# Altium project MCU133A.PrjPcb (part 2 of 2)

## Sheet MCU133A_USB_and_Power.SchDoc
size 431 x 279 mm; Date: Not shown in title block; ApprovedBy: Not shown in title block; CheckedBy: Not shown in title block; Author: Not shown in title block; CompanyName: Not shown in title block; Engineer: Not shown in title block; Organization: Not shown in title block; Address1: Not shown in title block; Address2: Not shown in title block; Address3: Not shown in title block; Address4: Not shown in title block; DocumentNumber: 6; Revision: Use project parameter SCH_Rev; SheetNumber: 6; SheetTotal: 7; PageSetup: Record=PageOptions¦CenterHorizontal=True¦CenterVertical=True¦PrintScale=1.00¦XCorrection=1.00¦YCorrection=1.00¦PrintKind=0¦BorderSize=5000000¦LeftOffset=0¦BottomOffset=0¦Orientation=2¦PaperLength=1000¦PaperWidth=1000¦Scale=100¦PaperSource=15¦PrintQuality=600¦MediaType=1¦DitherType=10¦PaperKind=Letter¦PrintScaleMode=1
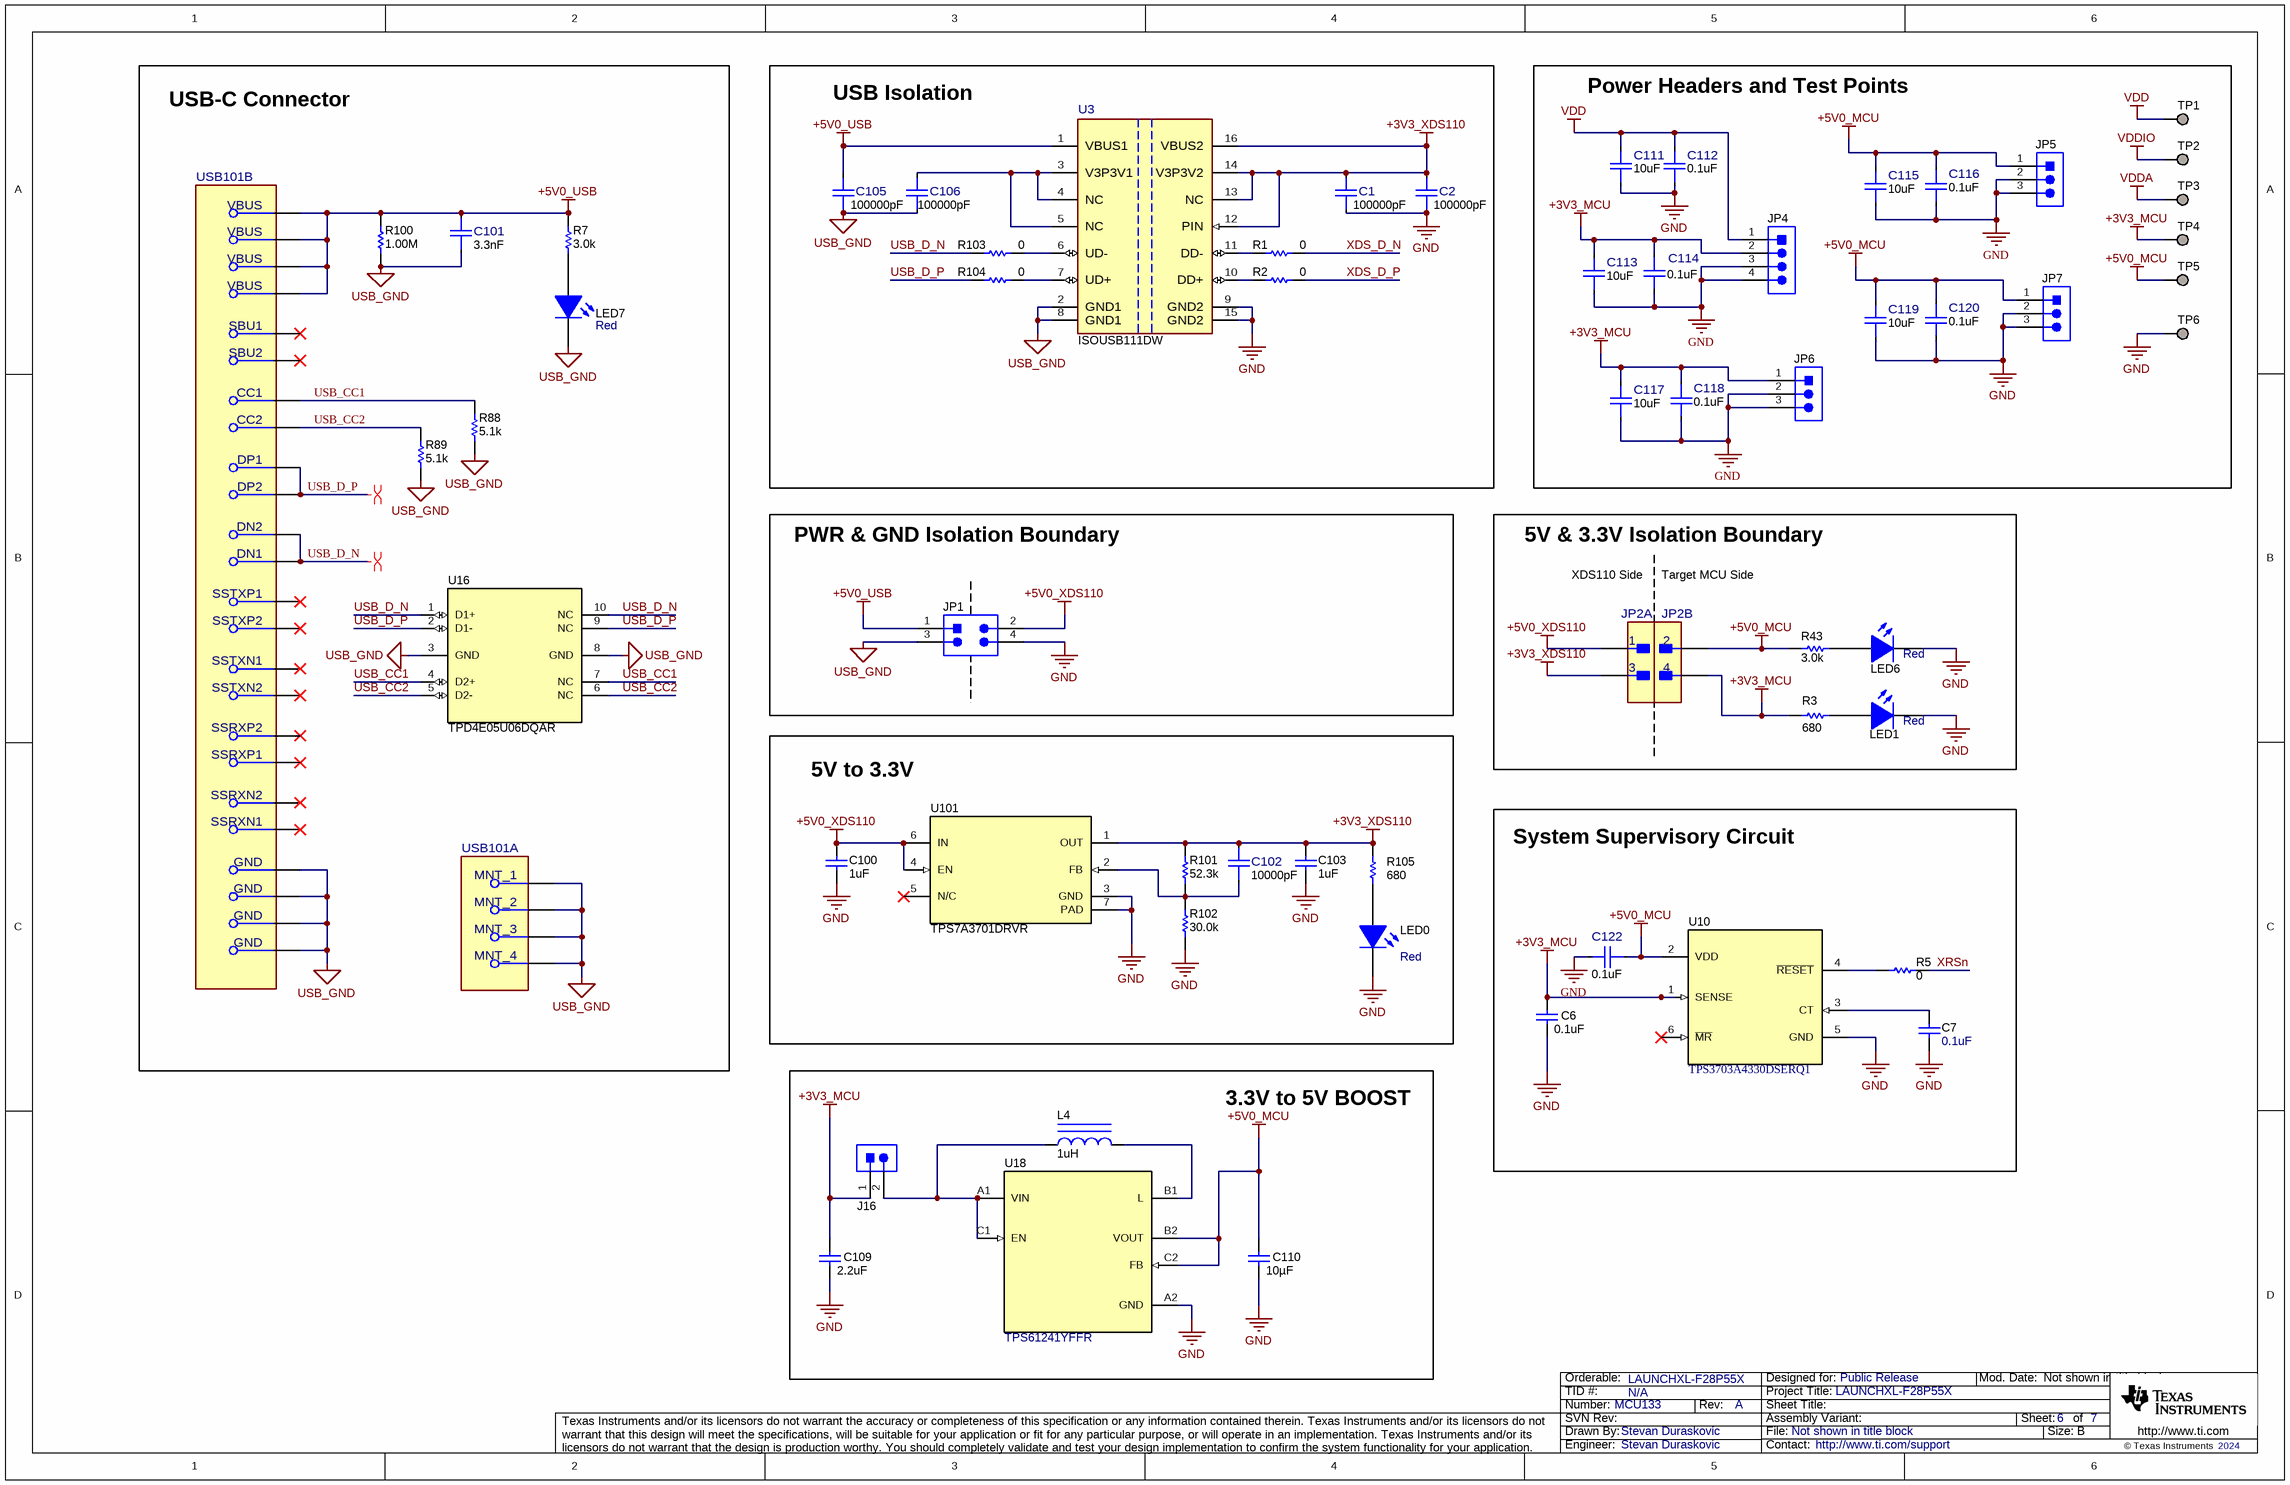
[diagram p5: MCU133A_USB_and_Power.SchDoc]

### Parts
C1  ValueDisplayed: 100000pF  [FP-885012205018_0402-MFG]  (hidden comment: 885012205018)
C2  ValueDisplayed: 100000pF  [FP-885012205018_0402-MFG]  (hidden comment: 885012205018)
C6  ValueDisplayed: 0.1uF  [0402]  (hidden comment: 885012205037)
C7  ValueDisplayed: 0.1uF  [0402]  (hidden comment: 885012205037)
C100  ValueDisplayed: 1uF  [0402]  (hidden comment: 885012105012)
C101  ValueDisplayed: 3.3nF  [FP-885012205064_0402-MFG]  (hidden comment: 885012205064)
C102  ValueDisplayed: 10000pF  [FP-885012205050_0402-MFG]  (hidden comment: 885012205050)
C103  ValueDisplayed: 1uF  [0402]  (hidden comment: 885012105012)
C105  ValueDisplayed: 100000pF  [FP-885012205018_0402-MFG]  (hidden comment: 885012205018)
C106  ValueDisplayed: 100000pF  [FP-885012205018_0402-MFG]  (hidden comment: 885012205018)
C109  ValueDisplayed: 2.2uF  [0603]  (hidden comment: 885012106018)
C110  ValueDisplayed: 10µF  [0603]  (hidden comment: GRM188R61C106KAALD)
C111  ValueDisplayed: 10uF  [FP-CC0603KRX5R6BB106_0603-MFG]  (hidden comment: CC0603KRX5R6BB106)
C112  ValueDisplayed: 0.1uF  [FP-885012205018_0402-MFG]  (hidden comment: 885012205018)
C113  ValueDisplayed: 10uF  [FP-CC0603KRX5R6BB106_0603-MFG]  (hidden comment: CC0603KRX5R6BB106)
C114  ValueDisplayed: 0.1uF  [FP-885012205018_0402-MFG]  (hidden comment: 885012205018)
C115  ValueDisplayed: 10uF  [FP-CC0603KRX5R6BB106_0603-MFG]  (hidden comment: CC0603KRX5R6BB106)
C116  ValueDisplayed: 0.1uF  [FP-885012205018_0402-MFG]  (hidden comment: 885012205018)
C117  ValueDisplayed: 10uF  [FP-CC0603KRX5R6BB106_0603-MFG]  (hidden comment: CC0603KRX5R6BB106)
C118  ValueDisplayed: 0.1uF  [FP-885012205018_0402-MFG]  (hidden comment: 885012205018)
C119  ValueDisplayed: 10uF  [FP-CC0603KRX5R6BB106_0603-MFG]  (hidden comment: CC0603KRX5R6BB106)
C120  ValueDisplayed: 0.1uF  [FP-885012205018_0402-MFG]  (hidden comment: 885012205018)
C122  ValueDisplayed: 0.1uF  [FP-885012205018_0402-MFG]  (hidden comment: 885012205018)
J16  61300211121  [WURTH_61300211121]  (value not drawn)
JP1  TSM-102-01-L-DV  [Samtec_TSM-102-01-x-DV]  (value not drawn)
JP2  61300421121  [FP-61300421121_HDR4-MFG]  (value not drawn)  (parts A,B of 2)
JP4  61300411121  [WURTH_61300411121]  (value not drawn)
JP5  61300311121  [WURTH_61300311121]  (value not drawn)
JP6  61300311121  [WURTH_61300311121]  (value not drawn)
JP7  61300311121  [WURTH_61300311121]  (value not drawn)
L4  ValueDisplayed: 1uH  [0805_HV]  (hidden comment: LQM21PN1R0MC0D)
LED0  value Red  [WL-SMCW_RED_0805]  (hidden comment: 150080SS75000)
LED1  value Red  [WL-SMCW_RED_0805]  (hidden comment: 150080SS75000)
LED6  value Red  [WL-SMCW_RED_0805]  (hidden comment: 150080SS75000)
LED7  value Red  [WL-SMCW_RED_0805]  (hidden comment: 150080SS75000)
R1  ValueDisplayed: 0  [0402]  (hidden comment: RC0402JR-070RL)
R2  ValueDisplayed: 0  [0402]  (hidden comment: RC0402JR-070RL)
R3  ValueDisplayed: 680  [0402]  (hidden comment: CRCW0402680RJNED)
R5  ValueDisplayed: 0  [0603]  (hidden comment: ERJ-3GEY0R00V)
R7  ValueDisplayed: 3.0k  [0603]  (hidden comment: RC0603JR-073KL)
R43  ValueDisplayed: 3.0k  [0603]  (hidden comment: RC0603JR-073KL)
R88  ValueDisplayed: 5.1k  [0603]  (hidden comment: RC0603JR-075K1L)
R89  ValueDisplayed: 5.1k  [0603]  (hidden comment: RC0603JR-075K1L)
R100  ValueDisplayed: 1.00M  [0402]  (hidden comment: CRCW04021M00FKED)
R101  ValueDisplayed: 52.3k  [0402]  (hidden comment: CRCW040252K3FKED)
R102  ValueDisplayed: 30.0k  [0402]  (hidden comment: CRCW040230K0FKED)
R103  ValueDisplayed: 0  [0402]  (hidden comment: RC0402JR-070RL)
R104  ValueDisplayed: 0  [0402]  (hidden comment: RC0402JR-070RL)
R105  ValueDisplayed: 680  [0402]  (hidden comment: CRCW0402680RJNED)
TP1  TESTPOINT  [TP_50MIL-25MILHOLE]  (value not drawn)  (no BOM)
TP2  TESTPOINT  [TP_50MIL-25MILHOLE]  (value not drawn)  (no BOM)
TP3  TESTPOINT  [TP_50MIL-25MILHOLE]  (value not drawn)  (no BOM)
TP4  TESTPOINT  [TP_50MIL-25MILHOLE]  (value not drawn)  (no BOM)
TP5  TESTPOINT  [TP_50MIL-25MILHOLE]  (value not drawn)  (no BOM)
TP6  TESTPOINT  [TP_50MIL-25MILHOLE]  (value not drawn)  (no BOM)
U3  ISOUSB111DW  [DW0016B-MFG]
U10  TPS3703A4330DSERQ1  [DSE0006A]
U16  TPD4E05U06DQAR  [DQA0010A]
U18  TPS61241YFFR  [YFF0006AEAE]
U101  TPS7A3701DRVR  [DRV0006A]
USB101  MUP-U22001  [FP-MUP-U22001_CONN_USB_8MM94_8MM0-MFG]  (value not drawn)  (parts A,B of 2)

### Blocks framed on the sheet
USB-C Connector: C101 LED7 R7 R88 R89 R100 U16 USB101
USB Isolation: C1 C2 C105 C106 R1 R2 R103 R104 U3
Power Headers and Test Points: C111-C120 JP4-JP7 TP1-TP6
PWR & GND Isolation Boundary: JP1
5V & 3.3V Isolation Boundary: JP2 LED1 LED6 R3 R43
5V to 3.3V: C100 C102 C103 LED0 R101 R102 R105 U101
System Supervisory Circuit: C6 C7 C122 R5 U10
3.3V to 5V BOOST: C109 C110 J16 L4 U18

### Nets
+3V3_MCU: C6.1 C109.1 C113.2 C114.1 C117.2 C118.1 J16.1 JP2.4 JP4.2 JP6.1 R3.2 TP4.1 U10.1(SENSE)
+3V3_XDS110: C1.2 C2.2 C102.2 C103.1 JP2.3 R101.2 R105.2 U3.12(PIN) U3.13(NC) U3.14(V3P3V2) U3.16(VBUS2) U101.1(OUT)
+5V0_MCU: C110.1 C115.2 C116.1 C119.2 C120.1 C122.1 JP2.2 JP5.1 JP7.1 R43.2 TP5.1 U10.2(VDD) U18.B2(VOUT) U18.C2(FB)
+5V0_USB: C101.2 C105.2 JP1.1 R7.2 R100.2 U3.1(VBUS1) USB101.A4(VBUS) USB101.A9(VBUS) USB101.B4(VBUS) USB101.B9(VBUS)
+5V0_XDS110: C100.1 JP1.2 JP2.1 U101.4(EN) U101.6(IN)
GND: C1.1 C2.1 C6.2 C7.2 C100.2 C103.2 C109.2 C110.2 C111.1 C112.1 C113.1 C114.2 C115.1 C116.2 C117.1 C118.2 C119.1 C120.2 C122.2 JP1.4 JP4.3 JP4.4 JP5.2 JP5.3 JP6.2 JP6.3 JP7.2 JP7.3 LED0.1(K) LED1.1(K) LED6.1(K) R102.1 TP6.1 U3.9(GND2) U3.15(GND2) U10.5(GND) U18.A2(GND) U101.3(GND) U101.7(PAD)
USB_GND: C101.1 C105.1 C106.1 JP1.3 LED7.1(K) R88.1 R89.1 R100.1 U3.2(GND1) U3.8(GND1) U16.3(GND) U16.8(GND) USB101.1(MNT_1) USB101.2(MNT_2) USB101.3(MNT_3) USB101.4(MNT_4) USB101.A1(GND) USB101.A12(GND) USB101.B1(GND) USB101.B12(GND)
VDD: C111.2 C112.2 JP4.1 TP1.1
VDDA: TP3.1
VDDIO: TP2.1
USB_CC1: R88.2 U16.4(D2+) U16.7(NC) USB101.A5(CC1)
USB_CC2: R89.2 U16.5(D2-) U16.6(NC) USB101.B5(CC2)
USB_D_N: R103.1 U16.1(D1+) U16.10(NC) USB101.A7(DN1) USB101.B7(DN2)
USB_D_P: R104.1 U16.2(D1-) U16.9(NC) USB101.A6(DP1) USB101.B6(DP2)
XDS_D_N: R1.2
XDS_D_P: R2.2
XRSn: R5.1
NetC7_1: C7.1 U10.3(CT)
NetC102_1: C102.1 R101.1 R102.2 U101.2(FB)
NetC106_2: C106.2 U3.3(V3P3V1) U3.4(NC) U3.5(NC)
NetJ16_2: J16.2 L4.1 U18.A1(VIN) U18.C1(EN)
NetL4_2: L4.2 U18.B1(L)
NetLED0_2: LED0.2(A) R105.1
NetLED1_2: LED1.2(A) R3.1
NetLED6_2: LED6.2(A) R43.1
NetLED7_2: LED7.2(A) R7.1
NetR1_1: R1.1 U3.11(DD-)
NetR2_1: R2.1 U3.10(DD+)
NetR5_2: R5.2 U10.4(~{RESET})
NetR103_2: R103.2 U3.6(UD-)
NetR104_2: R104.2 U3.7(UD+)

Not connected (* = marked no-connect by the designer): U10 6(~{MR})*; U101 5(N/C)*; USB101 A2(SSTXP1)* A3(SSTXN1)* A8(SBU1)* A10(SSRXN2)* A11(SSRXP2)* B2(SSTXP2)* B3(SSTXN2)* B8(SBU2)* B10(SSRXN1)* B11(SSRXP1)*

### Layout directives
differential pair: USB_D_N, USB_D_P

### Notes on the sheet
- XDS110 Side
- Target MCU Side

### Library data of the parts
C1 C2 C105 C106 C112 C114 C116 C118 C120 C122 = CMP-0090362-1: 0.1µF ±10% 10V Ceramic Capacitor X7R 0402 (1005 Metric); Manufacturer: Wurth Electronics; AEC Qualified: No; Value: 100nF; SizeZ_mm: 0.55mm; TempCo: 15%
C6 C7 = CMP-0006228-2: CAP, CERM, 0.1 uF, 16 V, +/- 10%, X7R, 0402; Manufacturer: Wurth Elektronik; TaMin_C: -55°C; Polarized: N; SizeAreaWB_mm2: 3; Value1: Unknown; U/M: EA; Value: 0.1uF; TaMax_C: 125°C; SizeZ_mm: 0.6; SizeX_mm: 1; SizeY_mm: 0.5; Value2: 16V; Cap_F: 100nF; AEC Category: Q200
C100 C103 = CMP-0064924-2: CAP, CERM, 1 uF, 10 V,+/- 20%, X5R, 0402; Manufacturer: Wurth Elektronik; Polarized: N; Value: 1uF; U/M: EA; Cap_F: 1µF; Value1: Unknown; VDC_V: 10V; TaMin_C: -55°C; TaMax_C: 85°C; SizeArea_mm2: 0.5; SizeAreaWB_mm2: 3; SizeX_mm: 1; SizeZ_mm: 0.6; AEC Category: Q200
C101 = CMP-0092424-1: Cap Cer 3300pF 50V X7R 0402; Manufacturer: Wurth Electronics; TempCo: 15%; AEC Qualified: No; Value: 3.3nF; SizeZ_mm: 0.55mm; Tolerance_%: 10%
C102 = CMP-0090363-1: 10000pF ±10% 25V Ceramic Capacitor X7R 0402 (1005 Metric); Manufacturer: Wurth Electronics; SizeZ_mm: 0.55mm; Cap_F: 10nF; AEC Qualified: No; Value: 10nF; TempCo: 15%
C109 = CMP-0006825-5: CAP, CERM, 2.2 uF, 16 V, +/- 20%, X5R, 0603; Manufacturer: Wurth Elektronik; TaMin_C: -55°C; Polarized: N; SizeAreaWB_mm2: 4.68; Value1: Unknown; U/M: EA; Value: 2.2uF; TaMax_C: 85°C; SizeZ_mm: 1; SizeX_mm: 1.6; SizeY_mm: 0.8; Value2: 16V; SizeArea_mm2: 1.28; Cap_F: 2.2µF; AEC Category: Q200
C110 = CMP-0086225-1: CAP, CERM, 10 µF, 16 V,+/- 10%, X5R, 0603; Manufacturer: MuRata; SizeZ_mm: 1; SizeX_mm: 1.6; SizeArea_mm2: 1.28; VDC_V: 16V; U/M: EA; AEC Category: Q200; SizeY_mm: 0.8; Polarized: N; TaMax_C: 85°C; Value: 10uF; SizeAreaWB_mm2: 4.68; TaMin_C: -55°C
C111 C113 C115 C117 C119 = CMP-0092309-1: Cap Ceramic 10uF 10V X5R 10% SMD 0603 85C Paper T/R; Manufacturer: YAGEO; Cap_F: 10µF; TempCo: 15%; Category 7542B8484461Ae85: Passive Components; Category 4C11811B7D3097D6: Single Components; SizeZ_mm: 1mm; Category F8883582C9A8234F: Capacitors; AEC Qualified: No; Value: 10µF; Category 85Ce48C4B2B95E09: Uncategorized
J16 = CMP-0054794-2: Header, 2.54 mm, 2x1, Gold, TH; Manufacturer: Wurth Elektronik; Shrouded: N; Gender: Male; Green_REACh: Passed; Pitch_mm: 2.54; Green_Lifecycle: Active; Row_Count: 1; Cert_UL: Y
JP1 = CMP-0055559-1: Header, 2.54mm, 2x2, Gold, SMT; Manufacturer: Samtec; CNHeader: TRUE; Shrouded: N; Gender: Male; Cert_CSA: Y; Voltage_V: 475V; Row_Count: 2; Pitch_mm: 2.54; CT: FALSE
JP2 = CMP-0092422-1: THT Vertical Pin Header WR-PHD, Pitch 2.54 mm, Dual Row, 4 pins; Manufacturer: Wurth Electronics; DUT-Pitch_mm: 2.54mm; SizeZ_mm: 8.89mm; Voltage_V: 250V; Conn Gender: Male; AEC Qualified: No; Row_Count: 2; ContactFinish: Gold; Conn Orientation: Straight; Current_A: 3A
JP4 = CMP-0054798-2: Header, 2.54 mm, 4x1, Gold, TH; Manufacturer: Wurth Elektronik; Pitch_mm: 2.54; Gender: Male; Row_Count: 1; Cert_UL: Y; Shrouded: N
JP5-JP7 = CMP-0054796-1: Header, 2.54 mm, 3x1, Gold, TH; Manufacturer: Wurth Elektronik; Green_Lifecycle: Active; Green_REACh: Passed; CNHeader: TRUE; CT: FALSE
L4 = CMP-0058739-1: Inductor, Multilayer, Ferrite, 1 uH, 0.8 A, 0.19 ohm, SMD; Manufacturer: MuRata; Irms: 0.8A @ 40C rise; Green_Lifecycle: Active; SizeAreaWB_mm2: 6.75; DCR_ohm: 1.9d; Green_REACh: Passed; Value: 1uH; Imax_A: 8dA; SizeZ_mm: 1.45; SizeX_mm: 2; SizeY_mm: 1.25; Value2: 0.8A; SizeArea_mm2: 2.5; Ind_H: 1µH; AEC Category: Q200
LED0 LED1 LED6 LED7 = CMP-0002951-3: LED, Red, SMD; Manufacturer: Wurth Elektronik; Type: AlInGaP; Vf_V: 1.9V; Io_A: 30mA; Vr_V: 5V; Ir_A: 25µA; Tjmax_C: 85°C; Power_TotalModule: 72mW; Value1: 0.072W; Angle: 140
R1 R2 R103 R104 = CMP-0027004-2: RES, 0, 5%, 0.063 W, 0402; Manufacturer: Yageo America; Power_W: 63mW; TempCo: 200 ppm/C; Value_Code: 0000; U/M: EA; Value: 0; EIA_Code: E24; SizeX_mm: 1; SizeY_mm: 0.5; SizeZ_mm: 0.6; Value2: 0.063W; VDC_V: 50V; AEC Category: Q200
R3 R105 = CMP-0026962-3: RES, 680, 5%, 0.063 W, AEC-Q200 Grade 0, 0402; Manufacturer: Vishay-Dale; Power_W: 63mW; TempCo: 200 ppm/C; Value_Code: 680R; Value: 680; EIA_Code: E24; SizeX_mm: 1; SizeY_mm: 0.5; SizeZ_mm: 0.6; Value2: 0.063W; AEC Qualified: Y; VDC_V: 50V; AEC Category: Q200; AEC Grade: 0
R5 = CMP-0025874-4: RES, 0, 5%, 0.1 W, AEC-Q200 Grade 0, 0603; Manufacturer: Panasonic; Power_W: 100mW; TempCo: 600 ppm/C; Value_Code: 0000; Value: 0; EIA_Code: E24; SizeX_mm: 1.6; SizeY_mm: 0.8; SizeZ_mm: 1; Value2: 0.1W; SizeArea_mm2: 1.28; AEC Qualified: Y; VDC_V: 50V; AEC Category: Q200; SizeAreaWB_mm2: 4.68
R7 R43 = CMP-0025921-5: RES, 3.0 k, 5%, 0.1 W, 0603; Manufacturer: Yageo; Power_W: 100mW; TempCo: 100 ppm/C; Value_Code: 3k00; Value: 3.0k; EIA_Code: E24; Res_ohm: 3k; SizeX_mm: 1.6; SizeY_mm: 0.8; SizeZ_mm: 1; Value2: 0.1W; SizeArea_mm2: 1.28; AEC Qualified: N; VDC_V: 75V; AEC Category: Q200; SizeAreaWB_mm2: 4.68
R88 R89 = CMP-0025932-5: RES, 5.1 k, 5%, 0.1 W, 0603; Manufacturer: Yageo; Power_W: 100mW; TempCo: 100 ppm/C; Value_Code: 5k10; Value: 5.1k; EIA_Code: E24; SizeX_mm: 1.6; SizeY_mm: 0.8; SizeZ_mm: 1; Value2: 0.1W; SizeArea_mm2: 1.28; AEC Qualified: N; VDC_V: 75V; AEC Category: Q200; SizeAreaWB_mm2: 4.68
R100 = CMP-0026100-2: RES, 1.00 M, 1%, 0.063 W, AEC-Q200 Grade 0, 0402; Manufacturer: Vishay-Dale; Value: 1.00Meg; Res_ohm: 1M; Value_Code: 1M00; Power_W: 63mW; Value2: 0.063W; VDC_V: 50V; TempCo: 100 ppm/C; SizeArea_mm2: 0.5; SizeX_mm: 1; SizeZ_mm: 0.6; EIA_Code: E96; AEC Category: Q200; AEC Qualified: Y; AEC Grade: 0
R101 = CMP-0026441-2: RES, 52.3 k, 1%, 0.063 W, AEC-Q200 Grade 0, 0402; Manufacturer: Vishay-Dale; Power_W: 63mW; TempCo: 100 ppm/C; Value_Code: 52k3; Value: 52.3k; EIA_Code: E96; SizeX_mm: 1; SizeY_mm: 0.5; SizeZ_mm: 0.6; Value2: 0.063W; AEC Qualified: Y; VDC_V: 50V; AEC Category: Q200; AEC Grade: 0
R102 = CMP-0078244-2: RES, 30.0 k, 1%, 0.063 W, AEC-Q200 Grade 0, 0402; Manufacturer: Vishay-Dale; Power_W: 63mW; Green_Lifecycle: Active; TempCo: 100 ppm/C; Value_Code: 30k0; Green_REACh: Passed; Value: 30.0k; Res_ohm: 30k; SizeX_mm: 1; SizeY_mm: 0.5; SizeZ_mm: 0.6; Value2: 0.063W; AEC Qualified: Y; VDC_V: 50V; AEC Grade: 0; AEC Category: Q200
TP1-TP6 = CMP-0078143-3: TEST POINT.  No entry in BOM.
U3 = CMP-0091303-1: Full/Low Speed Isolated USB Repeater, SOIC16-Wide; Manufacturer: Texas Instruments; Number Of Ports: 1; Usb Standard: USB 2.0; Min Supply Voltage: 3V; Data Rate: 12Mbits/s; Max Supply Voltage: 5.5V; TaMin_C: -40°C; SizeZ_mm: 2.65mm; TaMax_C: +125°C; Nominal Supply Current: 9-9.5mA; TJmax_C: +150°C; Standoff Height: 0.1mm; AEC Qualified: No
U10 = CMP-0750051-1: Overvoltage and Undervoltage Reset IC With Time Delay and Manual Reset, DSE0006A (WSON-6); Alternate Manufacturer: Texas Instruments; AEC Category: Q200; SizeY_mm: 1.5; AEC Qualified: Y; SizeAreaWB_mm2: 6.25; SizeZ_mm: 0.8; SizeArea_mm2: 2.25
U16 = CMP-0073613-3: 4-Channel Ultra-Low-Capacitance IEC ESD Protection Diode, DQA0010A (USON-10); Alternate Manufacturer: Texas Instruments; Green_Lifecycle: Active; SizeAreaWB_mm2: 7.0; Green_REACh: Passed; SizeZ_mm: 0.55; SizeX_mm: 1.0; SizeY_mm: 2.5; CompType: IC; AEC Category: Q200; AEC Qualified: N
U18 = CMP-0067212-2: 5V, 500mA, 4MHz Step-Up DC/DC Converter, YFF0006AEAE (DSBGA-6); Alternate Manufacturer: Texas Instruments; Alternate PartNumber: TPS61241YFFT; AEC Qualified: N; Rating: Catalog; SizeX_mm: 0.856; SizeAreaWB_mm2: 4.190848; SizeY_mm: 1.258; SizeArea_mm2: 1.076848; AEC Category: Q200; CompType: IC; SizeZ_mm: 0.625
U101 = CMP-0066914-5: 1% High-Accuracy, 1-A, Low-Dropout Regulator with Reverse Current Protection, DRV0006A (WSON-6); Manufacturer: Texas Instruments; Alternate PartNumber: TPS7A3701DRVT; SizeX_mm: 2; CompType: IC; SizeZ_mm: 0.8; SizeArea_mm2: 4; SizeAreaWB_mm2: 9; U/M: EA
USB101 = CMP-0092137-1: Connector, USB Type-C 24 pin Mid Mount dual row Receptacle Surface Mount; Manufacturer: MUP; ContactFinish: Gold,Nickel; Usb Standard: OTHER; AEC Qualified: No; Conn Orientation: Horizontal; Shrouded: true; SizeZ_mm: 2.81mm; Is Female: yes; DUT-Pitch_mm: 0.5mm

## Sheet MCU133A_XDS110_MCU.SchDoc
size 431 x 279 mm; Date: Not shown in title block; ApprovedBy: Not shown in title block; CheckedBy: Not shown in title block; Author: Not shown in title block; CompanyName: Not shown in title block; Engineer: Not shown in title block; Organization: Not shown in title block; Address1: Not shown in title block; Address2: Not shown in title block; Address3: Not shown in title block; Address4: Not shown in title block; DocumentNumber: 7; Revision: Use project parameter SCH_Rev; SheetNumber: 7; SheetTotal: 8; PageSetup: Record=PageOptions¦CenterHorizontal=True¦CenterVertical=True¦PrintScale=1.00¦XCorrection=1.00¦YCorrection=1.00¦PrintKind=0¦BorderSize=5000000¦LeftOffset=0¦BottomOffset=0¦Orientation=2¦PaperLength=1000¦PaperWidth=1000¦Scale=100¦PaperSource=15¦PrintQuality=600¦MediaType=1¦DitherType=10¦PaperKind=Letter¦PrintScaleMode=1
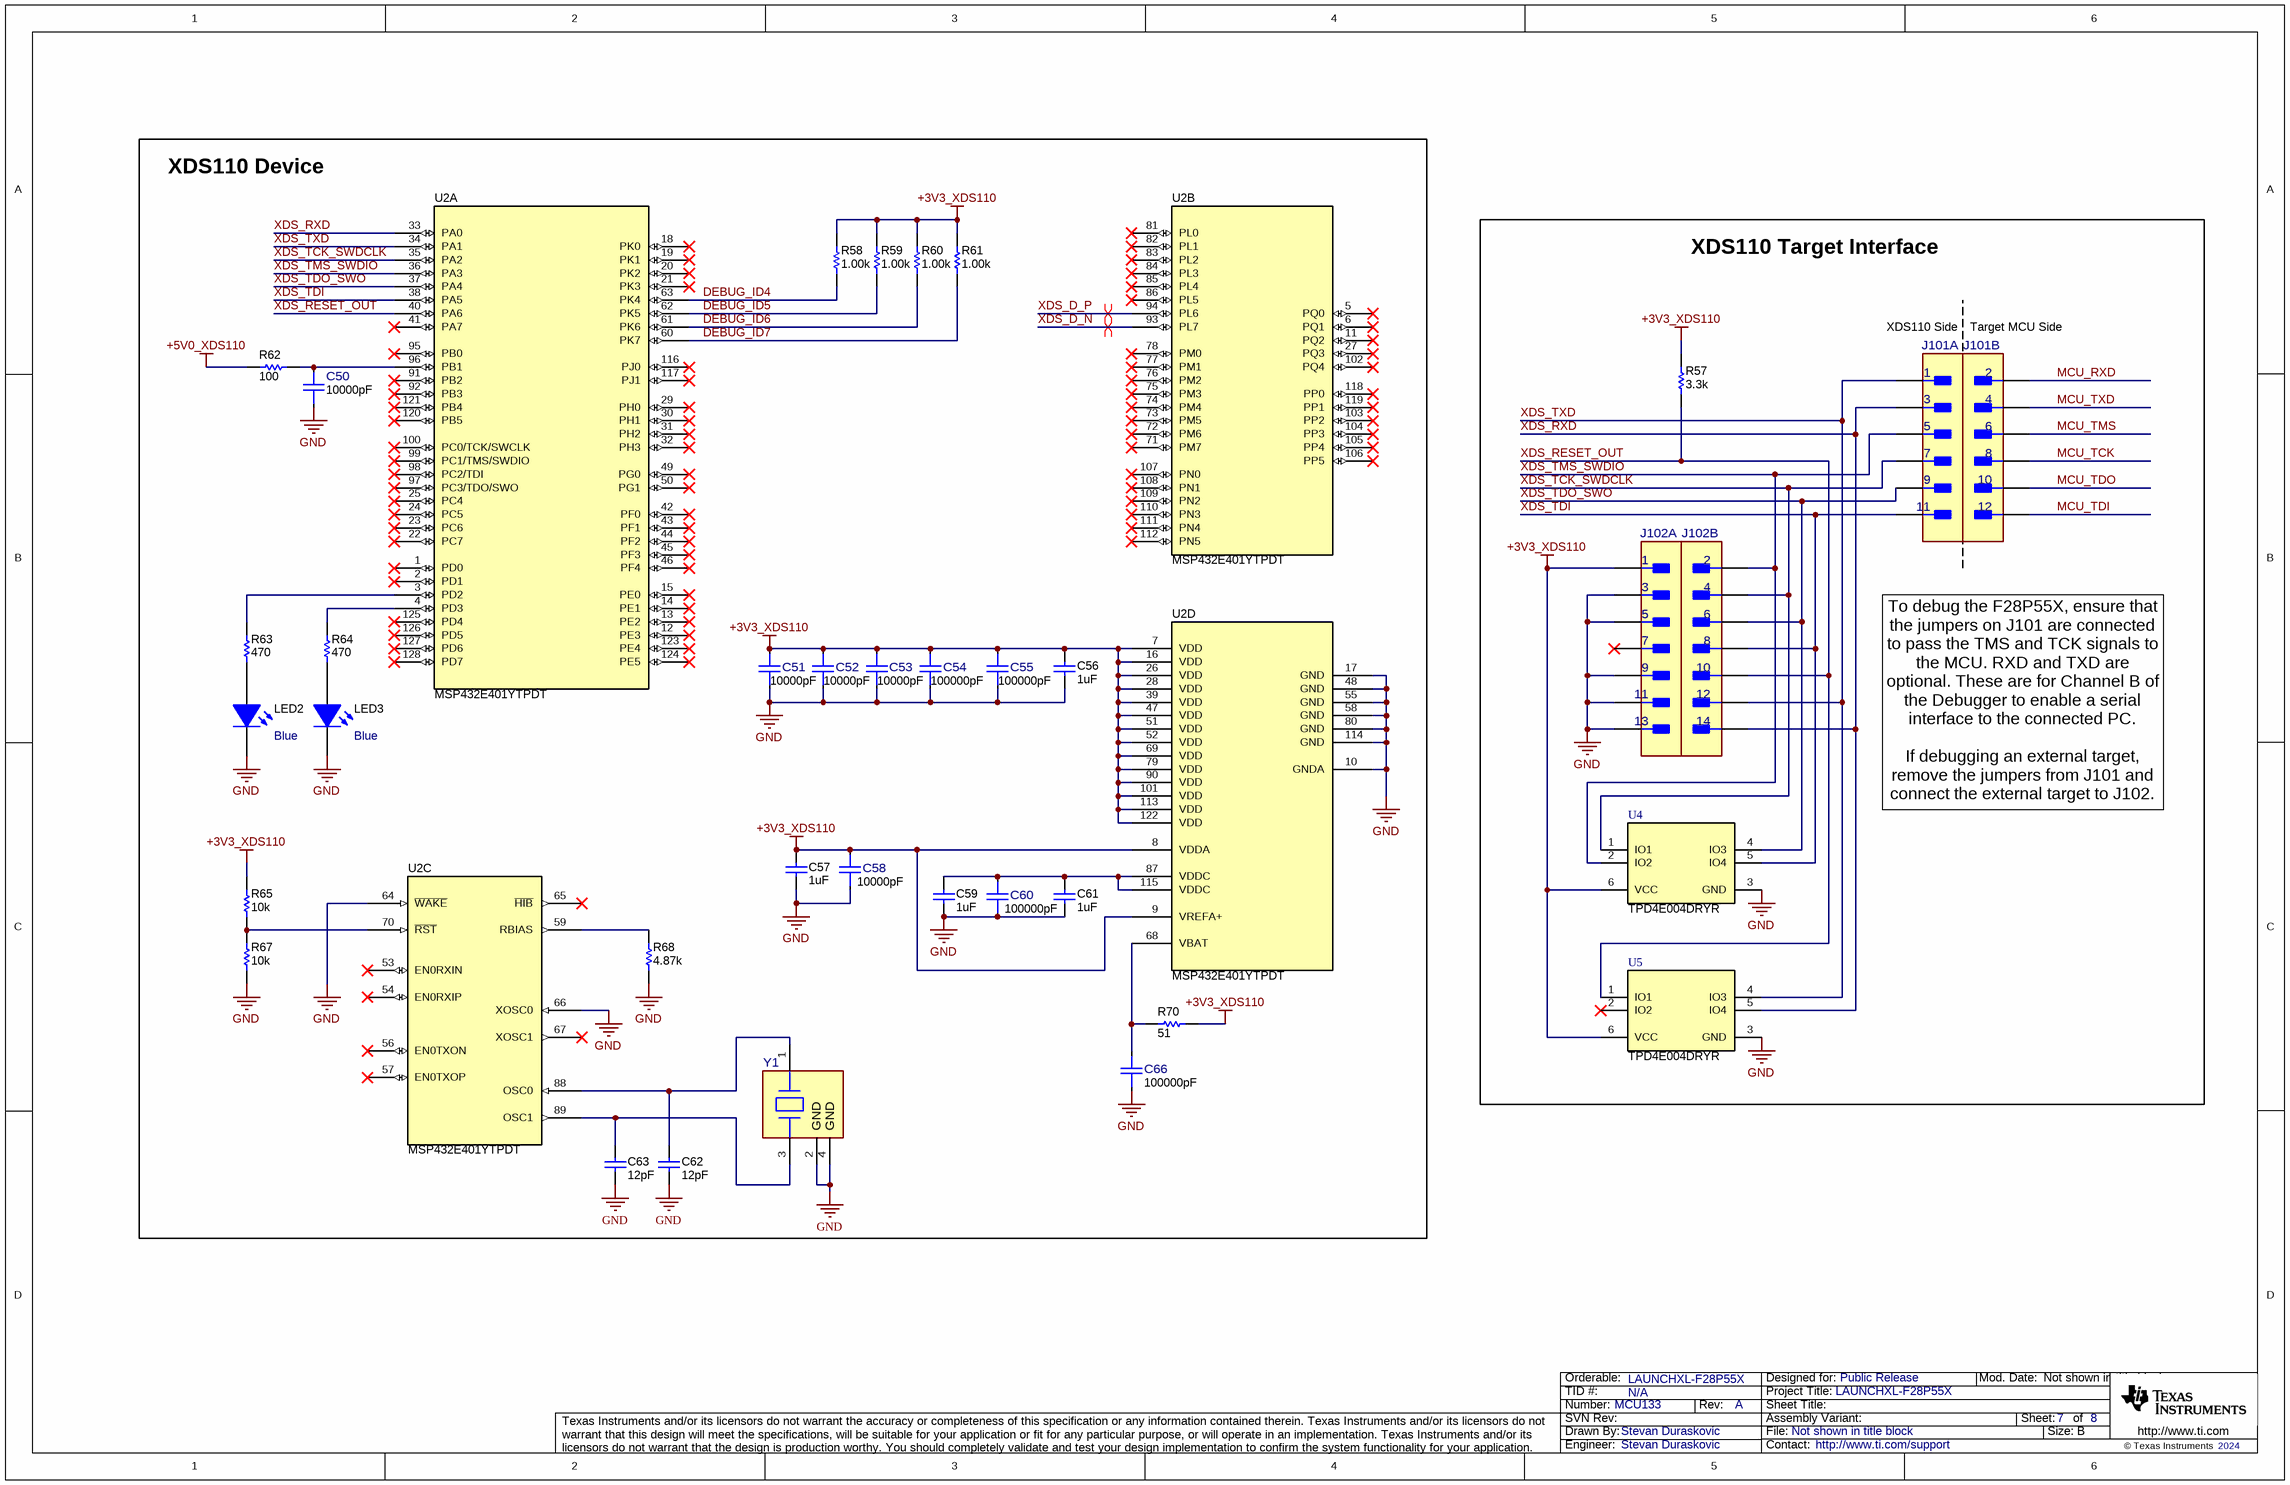
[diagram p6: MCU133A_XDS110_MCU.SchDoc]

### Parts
C50  ValueDisplayed: 10000pF  [FP-885012205050_0402-MFG]  (hidden comment: 885012205050)
C51  ValueDisplayed: 10000pF  [FP-885012205050_0402-MFG]  (hidden comment: 885012205050)
C52  ValueDisplayed: 10000pF  [FP-885012205050_0402-MFG]  (hidden comment: 885012205050)
C53  ValueDisplayed: 10000pF  [FP-885012205050_0402-MFG]  (hidden comment: 885012205050)
C54  ValueDisplayed: 100000pF  [FP-885012205018_0402-MFG]  (hidden comment: 885012205018)
C55  ValueDisplayed: 100000pF  [FP-885012205018_0402-MFG]  (hidden comment: 885012205018)
C56  ValueDisplayed: 1uF  [0402]  (hidden comment: 885012105012)
C57  ValueDisplayed: 1uF  [0402]  (hidden comment: 885012105012)
C58  ValueDisplayed: 10000pF  [FP-885012205050_0402-MFG]  (hidden comment: 885012205050)
C59  ValueDisplayed: 1uF  [0402]  (hidden comment: 885012105012)
C60  ValueDisplayed: 100000pF  [FP-885012205018_0402-MFG]  (hidden comment: 885012205018)
C61  ValueDisplayed: 1uF  [0402]  (hidden comment: 885012105012)
C62  ValueDisplayed: 12pF  [0402]  (hidden comment: CL05C120JB5NNNC)
C63  ValueDisplayed: 12pF  [0402]  (hidden comment: CL05C120JB5NNNC)
C66  ValueDisplayed: 100000pF  [FP-885012205018_0402-MFG]  (hidden comment: 885012205018)
J101  61301221121  [FP-61301221121_HDR12-MFG]  (value not drawn)  (parts A,B of 2)
J102  FTSH-107-01-F-DV-K  [FP-FTSH-107-01-F-DV-K_HDR14-MFG]  (value not drawn)  (parts A,B of 2)
LED2  value Blue  [LTST-C170TBKT_Blue]  (hidden comment: LTST-C170TBKT)
LED3  value Blue  [LTST-C170TBKT_Blue]  (hidden comment: LTST-C170TBKT)
R57  ValueDisplayed: 3.3k  [0402]  (hidden comment: CRCW04023K30JNED)
R58  ValueDisplayed: 1.00k  [0402]  (hidden comment: CRCW04021K00FKED)
R59  ValueDisplayed: 1.00k  [0402]  (hidden comment: CRCW04021K00FKED)
R60  ValueDisplayed: 1.00k  [0402]  (hidden comment: CRCW04021K00FKED)
R61  ValueDisplayed: 1.00k  [0402]  (hidden comment: CRCW04021K00FKED)
R62  ValueDisplayed: 100  [0402]  (hidden comment: CRCW0402100RJNED)
R63  ValueDisplayed: 470  [0402]  (hidden comment: RC0402FR-07470RL)
R64  ValueDisplayed: 470  [0402]  (hidden comment: RC0402FR-07470RL)
R65  ValueDisplayed: 10k  [0402]  (hidden comment: CRCW040210K0JNED)
R67  ValueDisplayed: 10k  [0402]  (hidden comment: CRCW040210K0JNED)
R68  ValueDisplayed: 4.87k  [0402]  (hidden comment: CRCW04024K87FKED)
R70  ValueDisplayed: 51  [0402]  (hidden comment: CRCW040251R0JNED)
U2  MSP432E401YTPDT  [PDT0128A]  (parts A,B,C,D of 4)
U4  TPD4E004DRYR  [DRY0006A]
U5  TPD4E004DRYR  [DRY0006A]
Y1  830064296  [FP-830064296_SMT4_3MM4_2MM7-MFG]  (value not drawn)

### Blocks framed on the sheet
XDS110 Device: C50-C63 C66 LED2 LED3 R58-R65 R67 R68 R70 U2 Y1
XDS110 Target Interface: J101 J102 R57 U4 U5

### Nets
+3V3_XDS110: C51.2 C52.2 C53.2 C54.2 C55.2 C56.1 C57.1 C58.2 J102.1 R57.2 R58.2 R59.2 R60.2 R61.2 R65.2 R70.2 U2.7(VDD) U2.8(VDDA) U2.9(VREFA+) U2.16(VDD) U2.26(VDD) U2.28(VDD) U2.39(VDD) U2.47(VDD) U2.51(VDD) U2.52(VDD) U2.69(VDD) U2.79(VDD) U2.90(VDD) U2.101(VDD) U2.113(VDD) U2.122(VDD) U4.6(VCC) U5.6(VCC)
+5V0_XDS110: R62.1
GND: C50.1 C51.1 C52.1 C53.1 C54.1 C55.1 C56.2 C57.2 C58.1 C59.2 C60.1 C61.2 C62.2 C63.2 C66.1 J102.3 J102.5 J102.9 J102.11 J102.13 LED2.2(K) LED3.2(K) R67.1 R68.1 U2.10(GNDA) U2.17(GND) U2.48(GND) U2.55(GND) U2.58(GND) U2.64(~{WAKE}) U2.66(XOSC0) U2.80(GND) U2.114(GND) U4.3(GND) U5.3(GND) Y1.2(GND) Y1.4(GND)
DEBUG_ID4: R58.1 U2.63(PK4)
DEBUG_ID5: R59.1 U2.62(PK5)
DEBUG_ID6: R60.1 U2.61(PK6)
DEBUG_ID7: R61.1 U2.60(PK7)
MCU_RXD: J101.2
MCU_TCK: J101.8
MCU_TDI: J101.12
MCU_TDO: J101.10
MCU_TMS: J101.6
MCU_TXD: J101.4
XDS_D_N: U2.93(PL7)
XDS_D_P: U2.94(PL6)
XDS_RESET_OUT: J102.10 R57.1 U2.40(PA6) U5.1(IO1)
XDS_RXD: J101.3 J102.14 U2.33(PA0) U5.5(IO4)
XDS_TCK_SWDCLK: J101.7 J102.4 U2.35(PA2) U4.1(IO1)
XDS_TDI: J101.11 J102.8 U2.38(PA5) U4.5(IO4)
XDS_TDO_SWO: J101.9 J102.6 U2.37(PA4) U4.4(IO3)
XDS_TMS_SWDIO: J101.5 J102.2 U2.36(PA3) U4.2(IO2)
XDS_TXD: J101.1 J102.12 U2.34(PA1) U5.4(IO3)
NetC50_2: C50.2 R62.2 U2.96(PB1)
NetC59_1: C59.1 C60.2 C61.1 U2.87(VDDC) U2.115(VDDC)
NetC62_1: C62.1 U2.88(OSC0) Y1.1(1_Crystal)
NetC63_1: C63.1 U2.89(OSC1) Y1.3(2_Crystal)
NetC66_2: C66.2 R70.1 U2.68(VBAT)
NetLED2_1: LED2.1(A) R63.1
NetLED3_1: LED3.1(A) R64.1
NetR63_2: R63.2 U2.3(PD2)
NetR64_2: R64.2 U2.4(PD3)
NetR65_1: R65.1 R67.2 U2.70(~{RST})
NetR68_2: R68.2 U2.59(RBIAS)

Not connected (* = marked no-connect by the designer): J102 7*; U2 1(PD0)* 2(PD1)* 5(PQ0)* 6(PQ1)* 11(PQ2)* 12(PE3)* 13(PE2)* 14(PE1)* 15(PE0)* 18(PK0)* 19(PK1)* 20(PK2)* 21(PK3)* 22(PC7)* 23(PC6)* 24(PC5)* 25(PC4)* 27(PQ3)* 29(PH0)* 30(PH1)* 31(PH2)* 32(PH3)* 41(PA7)* 42(PF0)* 43(PF1)* 44(PF2)* 45(PF3)* 46(PF4)* 49(PG0)* 50(PG1)* 53(EN0RXIN)* 54(EN0RXIP)* 56(EN0TXON)* 57(EN0TXOP)* 65(~{HIB})* 67(XOSC1)* 71(PM7)* 72(PM6)* 73(PM5)* 74(PM4)* 75(PM3)* 76(PM2)* 77(PM1)* 78(PM0)* 81(PL0)* 82(PL1)* 83(PL2)* 84(PL3)* 85(PL4)* 86(PL5)* 91(PB2)* 92(PB3)* 95(PB0)* 97(PC3/TDO/SWO)* 98(PC2/TDI)* 99(PC1/TMS/SWDIO)* 100(PC0/TCK/SWCLK)* 102(PQ4)* 103(PP2)* 104(PP3)* 105(PP4)* 106(PP5)* 107(PN0)* 108(PN1)* 109(PN2)* 110(PN3)* 111(PN4)* 112(PN5)* 116(PJ0)* 117(PJ1)* 118(PP0)* 119(PP1)* 120(PB5)* 121(PB4)* 123(PE4)* 124(PE5)* 125(PD4)* 126(PD5)* 127(PD6)* 128(PD7)*; U5 2(IO2)*

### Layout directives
differential pair: XDS_D_N, XDS_D_P

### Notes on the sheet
- (near J101) XDS110 Side
- (near J101) Target MCU Side
- To debug the F28P55X, ensure that the jumpers on J101 are connected to pass the TMS and TCK signals to the MCU. RXD and TXD are optional. These are for Channel B of the Debugger to enable a serial interface to the connected PC.
  If debugging an external target, remove the jumpers from J101 and connect the external target to J102.

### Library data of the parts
C50-C53 C58 = CMP-0090363-1: as C102 on sheet MCU133A_USB_and_Power
C54 C55 C60 C66 = CMP-0090362-1: as C1 on sheet MCU133A_USB_and_Power
C56 C57 C59 C61 = CMP-0064924-2: as C100 on sheet MCU133A_USB_and_Power
C62 C63 = CMP-0006345-2: CAP, CERM, 12 pF, 50 V, +/- 5%, C0G/NP0, 0402; Manufacturer: Samsung Electro-Mechanics; Polarized: N; Value: 12pF; U/M: EA; Value1: Unknown; VDC_V: 50V; TaMin_C: -55°C; TaMax_C: 125°C; SizeArea_mm2: 0.5; SizeAreaWB_mm2: 3; SizeX_mm: 1; SizeZ_mm: 0.6; AEC Category: Q200
J101 = CMP-0092423-1: THT Vertical Pin Header WR-PHD, Pitch 2.54 mm, Dual Row, 12 pins; Manufacturer: Wurth Electronics; Is Female: no; DUT-Pitch_mm: 2.54mm; Row_Count: 2; Current_A: 3A; Voltage_V: 250V; Conn Gender: Male; Conn Orientation: Straight; SizeZ_mm: 8.89mm; ContactFinish: Gold
J102 = CMP-0092335-1: Connector, Header, Dual Row, 14 pin, .05" pitch/row spacing, Male, Shrouded, Keyed, IDC, SMT; Manufacturer: Samtec; Category 0836C53C3D42D3F1: Connectors; Category 75Fab8F04590Ae3D: Connectors and Adapters; ContactFinish: Gold,Nickel; Standoff Height: 0.15mm; Conn Orientation: Vertical; AEC Qualified: No; Category E7012A0Bd22E3Cc6: Headers & Receptacles; SizeZ_mm: 6.38mm; Category A3C16Ecb93907806: Uncategorized; DUT-Pitch_mm: 1.27mm; Current_A: 3.4A; Row_Count: 2
LED2 LED3 = CMP-0002889-2: LED, Blue, SMD; Manufacturer: Lite-On; Type: AlInGaP; Vf_V: 3.3V; Io_A: 20mA; Value1: W
R57 = CMP-0026918-5: RES, 3.3 k, 5%, 0.063 W, AEC-Q200 Grade 0, 0402; Manufacturer: Vishay-Dale; Value: 3.3k; Value_Code: 3k30; Power_W: 63mW; Value2: 0.063W; VDC_V: 50V; TempCo: 200 ppm/C; SizeArea_mm2: 0.5; SizeX_mm: 1; SizeZ_mm: 0.6; EIA_Code: E24; AEC Category: Q200; AEC Qualified: Y; AEC Grade: 0
R58-R61 = CMP-0026071-3: RES, 1.00 k, 1%, 0.063 W, AEC-Q200 Grade 0, 0402; Manufacturer: Vishay-Dale; Power_W: 63mW; TempCo: 100 ppm/C; Value_Code: 1k00; Value: 1.00k; EIA_Code: E96; Res_ohm: 1k; SizeX_mm: 1; SizeY_mm: 0.5; SizeZ_mm: 0.6; Value2: 0.063W; AEC Qualified: Y; VDC_V: 50V; AEC Category: Q200; AEC Grade: 0
R62 = CMP-0026824-3: RES, 100, 5%, 0.063 W, AEC-Q200 Grade 0, 0402; Manufacturer: Vishay-Dale; Value: 100; Value_Code: 100R; Power_W: 63mW; Value2: 0.063W; VDC_V: 50V; TempCo: 200 ppm/C; SizeArea_mm2: 0.5; SizeX_mm: 1; SizeZ_mm: 0.6; EIA_Code: E24; AEC Category: Q200; AEC Qualified: Y; AEC Grade: 0
R63 R64 = CMP-0026736-1: RES, 470, 1%, 0.063 W, 0402; Manufacturer: Yageo America; Power_W: 63mW; TempCo: 100 ppm/C; Value_Code: 470R; U/M: EA; Value: 470; SizeX_mm: 1; SizeY_mm: 0.5; SizeZ_mm: 0.6; Value2: 0.063W; AEC Qualified: N; VDC_V: 50V; AEC Category: Q200
R65 R67 = CMP-0026825-5: RES, 10 k, 5%, 0.063 W, AEC-Q200 Grade 0, 0402; Manufacturer: Vishay-Dale; Value: 10k; Value_Code: 10k0; Power_W: 63mW; Value2: 0.063W; VDC_V: 50V; TempCo: 200 ppm/C; SizeArea_mm2: 0.5; SizeX_mm: 1; SizeZ_mm: 0.6; EIA_Code: E24; AEC Category: Q200; AEC Qualified: Y; AEC Grade: 0
R68 = CMP-0026413-2: RES, 4.87 k, 1%, 0.063 W, AEC-Q200 Grade 0, 0402; Manufacturer: Vishay-Dale; Value: 4.87k; Value_Code: 4k87; Power_W: 63mW; Value2: 0.063W; VDC_V: 50V; TempCo: 100 ppm/C; SizeArea_mm2: 0.5; SizeX_mm: 1; SizeZ_mm: 0.6; EIA_Code: E96; AEC Category: Q200; AEC Qualified: Y; AEC Grade: 0
R70 = CMP-0026946-3: RES, 51, 5%, 0.063 W, AEC-Q200 Grade 0, 0402; Manufacturer: Vishay-Dale; Value: 51; Value_Code: 51R0; Power_W: 63mW; Value2: 0.063W; VDC_V: 50V; TempCo: 200 ppm/C; SizeArea_mm2: 0.5; SizeX_mm: 1; SizeZ_mm: 0.6; EIA_Code: E24; AEC Category: Q200; AEC Qualified: Y; AEC Grade: 0
U2 = CMP-0077953-1: MSP432E401YTPDT, PDT0128A (TQFP-128); Alternate PartNumber: MSP432E401YTPDTR; Alternate Manufacturer: Texas Instruments; SizeAreaWB_mm2: 324; SizeZ_mm: 1.2; SizeX_mm: 16; SizeArea_mm2: 256; CompType: IC; AEC Qualified: N; AEC Category: Q200
U4 U5 = CMP-0043115-3: 4-Channel ESD Protection Array for High-Speed Data Interfaces, DRY0006A (USON-6); Manufacturer: Texas Instruments; IO Leakage Current(nA): 1; USB High Speed: TRUE; IO Capacitance(Typ)(pF): 1.6; Eco-Plan: Green (RoHS & no Sb/Br); IEC 61000-4-2 Contact(+/- kV): 8; Breakdown Voltage(Min)(V): 6; IEC 61000-4-2 Air-Gap(+/- kV): 12; AEC Category: Q200; AEC Qualified: N; CompType: IC; SizeAreaWB_mm2: 4.9; SizeArea_mm2: 1.45; SizeX_mm: 1.0; SizeZ_mm: 0.6; Rating: Catalog
Y1 = CMP-0094478-1: Crystal 16 MHz ±20ppm Crystal 8pF 70 Ohms 4-SMD, No Lead; Manufacturer: Wurth; SizeZ_mm: 0.8mm; Frequency_Fixed: 16MHz; Esr: 70

## Sheet MCU133A_Hardware.SchDoc
size 431 x 279 mm; Date: Not shown in title block; ApprovedBy: Not shown in title block; CheckedBy: Not shown in title block; Author: Not shown in title block; CompanyName: Not shown in title block; Engineer: Not shown in title block; Organization: Not shown in title block; Address1: Not shown in title block; Address2: Not shown in title block; Address3: Not shown in title block; Address4: Not shown in title block; DocumentNumber: 8; Revision: Use project parameter SCH_Rev; SheetNumber: 8; SheetTotal: 8; PageSetup: Record=PageOptions¦CenterHorizontal=True¦CenterVertical=True¦PrintScale=1.00¦XCorrection=1.00¦YCorrection=1.00¦PrintKind=0¦BorderSize=5000000¦LeftOffset=0¦BottomOffset=0¦Orientation=2¦PaperLength=1000¦PaperWidth=1000¦Scale=100¦PaperSource=15¦PrintQuality=600¦MediaType=1¦DitherType=10¦PaperKind=Letter¦PrintScaleMode=1
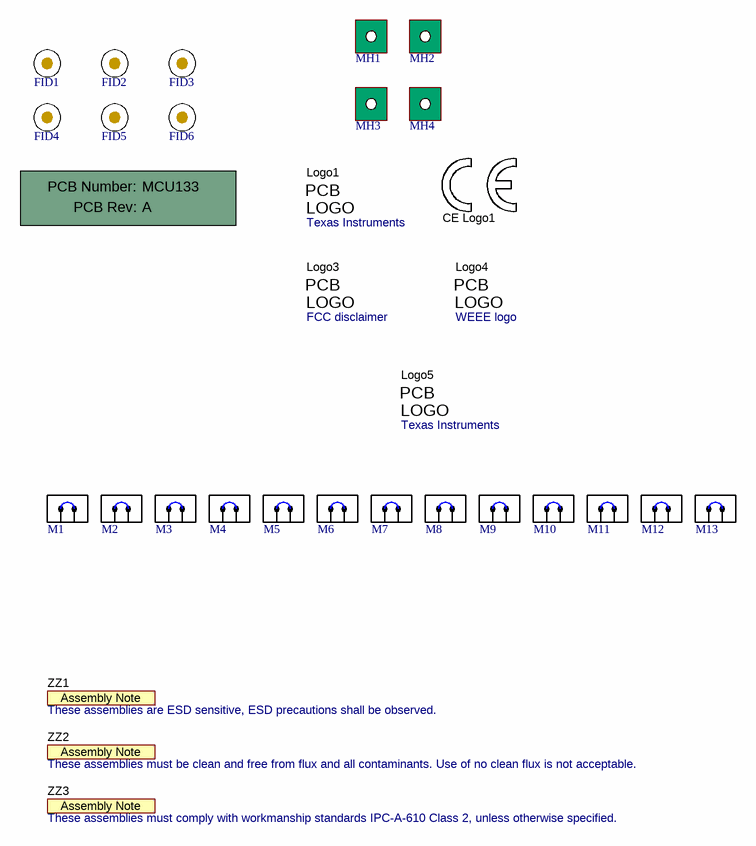
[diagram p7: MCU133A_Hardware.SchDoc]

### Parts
!PCB1  Printed Circuit Board  (value not drawn)  (mechanical)
CE_Logo1  CE Mark  [CE_Mark_5mm]  (value not drawn)  (no BOM)
FID1  Fiducial  [Fiducial10-20]  (value not drawn)
FID2  Fiducial  [Fiducial10-20]  (value not drawn)
FID3  Fiducial  [Fiducial10-20]  (value not drawn)
FID4  Fiducial  [Fiducial10-20]  (value not drawn)
FID5  Fiducial  [Fiducial10-20]  (value not drawn)
FID6  Fiducial  [Fiducial10-20]  (value not drawn)
Logo1  Texas Instruments  [TI_Stacked_Overlay_Medium]  (no BOM)
Logo3  FCC disclaimer  [FCC_disclaimer]  (no BOM)
Logo4  WEEE logo  [WEEE_Minimum]  (no BOM)
Logo5  Texas Instruments  [TI_Symbol_Overlay_Small]  (no BOM)
M1  60900213421  [Wurth_60900213421]  (value not drawn)
M2  60900213421  [Wurth_60900213421]  (value not drawn)
M3  60900213421  [Wurth_60900213421]  (value not drawn)
M4  60900213421  [Wurth_60900213421]  (value not drawn)
M5  60900213421  [Wurth_60900213421]  (value not drawn)
M6  60900213421  [Wurth_60900213421]  (value not drawn)
M7  60900213421  [Wurth_60900213421]  (value not drawn)
M8  60900213421  [Wurth_60900213421]  (value not drawn)
M9  60900213421  [Wurth_60900213421]  (value not drawn)
M10  60900213421  [Wurth_60900213421]  (value not drawn)
M11  60900213421  [Wurth_60900213421]  (value not drawn)
M12  60900213421  [Wurth_60900213421]  (value not drawn)
M13  60900213421  [Wurth_60900213421]  (value not drawn)
MH1  MTG_NoPads  [NPTH125mil]  (value not drawn)  (no BOM)
MH2  MTG_NoPads  [NPTH125mil]  (value not drawn)  (no BOM)
MH3  MTG_NoPads  [NPTH125mil]  (value not drawn)  (no BOM)
MH4  MTG_NoPads  [NPTH125mil]  (value not drawn)  (no BOM)
ZZ1  These assemblies are ESD sensitive, ESD precautions shall be observed.  [AssemblyNote]  (no BOM)
ZZ2  These assemblies must be clean and free from flux and all contaminants. Use of no clean flux is not acceptable.  [AssemblyNote]  (no BOM)
ZZ3  These assemblies must comply with workmanship standards IPC-A-610 Class 2, unless otherwise specified.  [AssemblyNote]  (no BOM)

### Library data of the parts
!PCB1 = CMP-0003618-2: Manufacturer: Any; PartNumber: MCU133
CE_Logo1 = CMP-0074844-1: SymbolCreator: a0412235
FID1-FID6 = CMP-0077181-1: Fiducial mark.  There is nothing to buy or mount.
Logo1 Logo5 = CMP-0074838-1: Texas Instrument Corporate Signature; SymbolCreator: a0412235; Lib Reference: TI_Logo
Logo3 = CMP-0074847-1: FCC_disclaimer
Logo4 = CMP-0074769-1
M1-M13 = CMP-0003761-2: Shunt, 2.54mm, Gold, Black; Manufacturer: Wurth Elektronik
MH1-MH4 = CMP-0078424-2: PCB Mounting Hole, No Pad; Manufacturer: Any; Key: Mounting Hole (non-standard) No Pad
ZZ1 = CMP-0077236-1
ZZ2 = CMP-0077237-1
ZZ3 = CMP-0077238-1

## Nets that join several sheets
+3V3_MCU: MCU133A_Connectors (5 pins), MCU133A_AltRouting_Misc (25 pins), MCU133A_F28P55x_Device (9 pins), MCU133A_USB_and_Power (13 pins)
+3V3_XDS110: MCU133A_USB_and_Power (12 pins), MCU133A_XDS110_MCU (34 pins)
+5V0_MCU: MCU133A_Connectors (10 pins), MCU133A_AltRouting_Misc (C65.2 C67.1 U13.23 U13.24), MCU133A_USB_and_Power (14 pins)
+5V0_XDS110: MCU133A_USB_and_Power (5 pins), MCU133A_XDS110_MCU (R62.1)
GND: MCU133A_Connectors (24 pins), MCU133A_AltRouting_Misc (38 pins), MCU133A_F28P55x_Device (22 pins), MCU133A_ADC (26 pins), MCU133A_USB_and_Power (39 pins), MCU133A_XDS110_MCU (37 pins)
VDD: MCU133A_F28P55x_Device (7 pins), MCU133A_USB_and_Power (C111.2 C112.2 JP4.1 TP1.1)
VDDA: MCU133A_F28P55x_Device (C14.2 C15.1 L2.2 U1.34), MCU133A_USB_and_Power (TP3.1)
VDDIO: MCU133A_F28P55x_Device (8 pins), MCU133A_USB_and_Power (TP2.1)
ADCINA0/B15/C15/DACA_OUT: MCU133A_Connectors (J5/J7.70), MCU133A_ADC (R12.1)
ADCINA1/B7/D11/DACB_OUT: MCU133A_Connectors (J1/J3.30), MCU133A_ADC (R13.1)
ADCINA4/B8: MCU133A_Connectors (J5/J7.66), MCU133A_ADC (R16.1)
ADCINA5: MCU133A_Connectors (J5/J7.65), MCU133A_ADC (R17.1)
ADCINA6/D14/E14: MCU133A_Connectors (J1/J3.23), MCU133A_ADC (R18.1)
ADCINA7/B30/C3/D12/E30: MCU133A_Connectors (J1/J3.6), MCU133A_ADC (R19.1)
ADCINA9: MCU133A_Connectors (J5/J7.46), MCU133A_ADC (R20.1)
ADCINA10/B1/C10: MCU133A_Connectors (J5/J7.64), MCU133A_ADC (R21.1)
ADCINA11/B10/C0/PGA2_OUT: MCU133A_Connectors (J1/J3.25), MCU133A_ADC (R22.1)
ADCINA12/C5: MCU133A_Connectors (J5/J7.69), MCU133A_ADC (R23.1)
ADCINA14/B14/C4/PGA1_OUT: MCU133A_Connectors (J1/J3.26), MCU133A_ADC (R24.1)
ADCINB0/C11: MCU133A_Connectors (J5/J7.63), MCU133A_ADC (R109.1)
ADCINB2/C6/E12: MCU133A_Connectors (J1/J3.24), MCU133A_ADC (R25.1)
ADCINB4/C8: MCU133A_Connectors (J5/J7.67), MCU133A_ADC (R27.1)
ADCINB5/D15/E15/PGA3_OUT: MCU133A_Connectors (J5/J7.68), MCU133A_ADC (R84.1)
ADCINC14: MCU133A_Connectors (J5/J7.42), MCU133A_ADC (R110.1)
ADCINPGA1_IN_N: MCU133A_AltRouting_Misc (U17.6), MCU133A_ADC (R15.1)
ADCINPGA1_IN_P: MCU133A_AltRouting_Misc (U17.4), MCU133A_ADC (R14.1)
ADCINPGA2_IN_N: MCU133A_AltRouting_Misc (U17.9), MCU133A_ADC (R86.1)
ADCINPGA2_IN_P: MCU133A_AltRouting_Misc (U17.7), MCU133A_ADC (R26.1)
ADCINPGA3_IN_N: MCU133A_AltRouting_Misc (U17.12), MCU133A_ADC (R85.1)
ADCINPGA3_IN_P: MCU133A_AltRouting_Misc (U17.10), MCU133A_ADC (R87.1)
EQEP1A: MCU133A_Connectors (C68.1 J12.1 R72.1), MCU133A_AltRouting_Misc (U13.21)
EQEP1B: MCU133A_Connectors (C69.1 J12.2 R73.1), MCU133A_AltRouting_Misc (U13.20)
EQEP1I: MCU133A_Connectors (C70.1 J12.3 R74.1), MCU133A_AltRouting_Misc (U13.19)
EQEP3A: MCU133A_Connectors (C71.1 J13.1 R75.1), MCU133A_AltRouting_Misc (U13.18)
EQEP3B: MCU133A_Connectors (C72.1 J13.2 R76.1), MCU133A_AltRouting_Misc (U13.17)
EQEP3I: MCU133A_Connectors (C73.1 J13.3 R77.1), MCU133A_AltRouting_Misc (U13.16)
GPIO0: MCU133A_Connectors (R8.1), MCU133A_F28P55x_Device (U1.79)
GPIO1: MCU133A_Connectors (R9.1), MCU133A_F28P55x_Device (U1.78)
GPIO2: MCU133A_Connectors (J4/J2.38), MCU133A_F28P55x_Device (U1.77)
GPIO3: MCU133A_Connectors (J4/J2.37), MCU133A_F28P55x_Device (U1.76)
GPIO4: MCU133A_AltRouting_Misc (S4.2), MCU133A_F28P55x_Device (U1.75)
GPIO4_BP: MCU133A_Connectors (J4/J2.32), MCU133A_AltRouting_Misc (S4.3)
GPIO4_CANTX: MCU133A_Connectors (TP7.1 U15.1), MCU133A_AltRouting_Misc (S4.1)
GPIO5: MCU133A_AltRouting_Misc (S4.5), MCU133A_F28P55x_Device (U1.89)
GPIO5_BP: MCU133A_Connectors (J4/J2.31), MCU133A_AltRouting_Misc (S4.6)
GPIO5_CANRX: MCU133A_Connectors (TP8.1 U15.4), MCU133A_AltRouting_Misc (S4.4)
GPIO6: MCU133A_Connectors (J8/J6.78), MCU133A_F28P55x_Device (U1.97)
GPIO7: MCU133A_Connectors (J8/J6.77), MCU133A_F28P55x_Device (U1.84)
GPIO8: MCU133A_Connectors (J4/J2.15), MCU133A_F28P55x_Device (U1.74)
GPIO9: MCU133A_Connectors (J1/J3.7), MCU133A_F28P55x_Device (U1.90)
GPIO10: MCU133A_Connectors (J4/J2.36), MCU133A_F28P55x_Device (U1.93)
GPIO11: MCU133A_Connectors (J4/J2.35), MCU133A_F28P55x_Device (U1.52)
GPIO12: MCU133A_Connectors (R49.1), MCU133A_F28P55x_Device (U1.51)
GPIO13: MCU133A_Connectors (R50.1), MCU133A_F28P55x_Device (U1.50)
GPIO14: MCU133A_Connectors (J5/J7.47), MCU133A_F28P55x_Device (U1.96)
GPIO15: MCU133A_AltRouting_Misc (U8.6), MCU133A_F28P55x_Device (U1.95)
GPIO15_BP: MCU133A_Connectors (J5/J7.43), MCU133A_AltRouting_Misc (U8.7)
GPIO16: MCU133A_Connectors (J8/J6.51), MCU133A_F28P55x_Device (U1.54)
GPIO17: MCU133A_Connectors (J4/J2.14), MCU133A_F28P55x_Device (U1.55)
GPIO18_BP: MCU133A_Connectors (J5/J7.49), MCU133A_AltRouting_Misc (R36.1)
GPIO18_X2: MCU133A_AltRouting_Misc (R32.1 R36.2), MCU133A_F28P55x_Device (U1.68)
GPIO19_BP: MCU133A_Connectors (J5/J7.50), MCU133A_AltRouting_Misc (R37.1)
GPIO19_X1: MCU133A_AltRouting_Misc (R33.1 R37.2), MCU133A_F28P55x_Device (U1.69)
GPIO20: MCU133A_Connectors (J8/J6.53), MCU133A_AltRouting_Misc (R34.1), MCU133A_F28P55x_Device (U1.48)
GPIO21: MCU133A_Connectors (J4/J2.13), MCU133A_AltRouting_Misc (R35.1), MCU133A_F28P55x_Device (U1.49)
GPIO22: MCU133A_Connectors (J4/J2.34), MCU133A_F28P55x_Device (U1.83)
GPIO23: MCU133A_Connectors (J4/J2.33), MCU133A_F28P55x_Device (U1.81)
GPIO24: MCU133A_Connectors (J1/J3.8), MCU133A_AltRouting_Misc (R38.1), MCU133A_F28P55x_Device (U1.56)
GPIO25: MCU133A_AltRouting_Misc (U11.14), MCU133A_F28P55x_Device (U1.57)
GPIO25_BP: MCU133A_Connectors (J8/J6.58), MCU133A_AltRouting_Misc (U11.13)
GPIO26: MCU133A_AltRouting_Misc (U11.15), MCU133A_F28P55x_Device (U1.58)
GPIO26_BP: MCU133A_Connectors (J8/J6.52), MCU133A_AltRouting_Misc (U11.1)
GPIO27: MCU133A_Connectors (J8/J6.59), MCU133A_F28P55x_Device (U1.59)
GPIO28: MCU133A_AltRouting_Misc (U6.10), MCU133A_F28P55x_Device (U1.1)
GPIO28_BP: MCU133A_Connectors (J1/J3.3), MCU133A_AltRouting_Misc (U6.2)
GPIO29: MCU133A_AltRouting_Misc (U6.6), MCU133A_F28P55x_Device (U1.100)
GPIO29_BP: MCU133A_Connectors (J1/J3.4 J1/J3.5), MCU133A_AltRouting_Misc (U6.4)
GPIO30: MCU133A_AltRouting_Misc (U11.4), MCU133A_F28P55x_Device (U1.98)
GPIO30_BP: MCU133A_Connectors (J8/J6.57), MCU133A_AltRouting_Misc (U11.3)
GPIO31: MCU133A_Connectors (J4/J2.17), MCU133A_F28P55x_Device (U1.99)
GPIO32: MCU133A_Connectors (J4/J2.18), MCU133A_AltRouting_Misc (R39.2), MCU133A_F28P55x_Device (U1.64)
GPIO33: MCU133A_Connectors (J8/J6.71), MCU133A_F28P55x_Device (U1.53)
GPIO34: MCU133A_Connectors (J1/J3.10), MCU133A_F28P55x_Device (U1.94)
GPIO35: MCU133A_Connectors (J8/J6.75), MCU133A_F28P55x_Device (R44.1 U1.63)
GPIO37: MCU133A_Connectors (J8/J6.76), MCU133A_F28P55x_Device (R45.1 U1.61)
GPIO40: MCU133A_AltRouting_Misc (U13.3), MCU133A_F28P55x_Device (U1.80)
GPIO41: MCU133A_AltRouting_Misc (U13.4), MCU133A_F28P55x_Device (U1.82)
GPIO44_FSITXCLK: MCU133A_Connectors (J11.2), MCU133A_F28P55x_Device (U1.85)
GPIO47: MCU133A_Connectors (J4/J2.12), MCU133A_F28P55x_Device (U1.6)
GPIO48: MCU133A_Connectors (J4/J2.11), MCU133A_F28P55x_Device (U1.7)
GPIO49_FSITXD0: MCU133A_Connectors (J11.6), MCU133A_F28P55x_Device (U1.8)
GPIO50_FSITXD1: MCU133A_Connectors (J11.8), MCU133A_F28P55x_Device (U1.9)
GPIO51: MCU133A_Connectors (J1/J3.9), MCU133A_F28P55x_Device (U1.10)
GPIO52_FSIRXD0: MCU133A_Connectors (J11.5), MCU133A_F28P55x_Device (U1.11)
GPIO53_FSIRXD1: MCU133A_Connectors (J11.7), MCU133A_F28P55x_Device (U1.12)
GPIO54_FSIRXCLK: MCU133A_Connectors (J11.1), MCU133A_F28P55x_Device (U1.13)
GPIO55: MCU133A_Connectors (J5/J7.48), MCU133A_F28P55x_Device (U1.43)
GPIO56: MCU133A_AltRouting_Misc (U8.10), MCU133A_F28P55x_Device (U1.65)
GPIO56_BP: MCU133A_Connectors (J5/J7.44 J5/J7.45), MCU133A_AltRouting_Misc (U8.9)
GPIO57: MCU133A_Connectors (J4/J2.19), MCU133A_F28P55x_Device (U1.66)
GPIO58: MCU133A_Connectors (J8/J6.72), MCU133A_F28P55x_Device (U1.67)
GPIO59: MCU133A_AltRouting_Misc (U13.5), MCU133A_F28P55x_Device (U1.92)
GPIO60: MCU133A_Connectors (J8/J6.55), MCU133A_F28P55x_Device (U1.44)
GPIO61: MCU133A_Connectors (J8/J6.54), MCU133A_F28P55x_Device (U1.91)
GPIO62: MCU133A_Connectors (J8/J6.74), MCU133A_F28P55x_Device (U1.46)
GPIO63: MCU133A_Connectors (J8/J6.73), MCU133A_F28P55x_Device (U1.47)
MCU_RXD: MCU133A_AltRouting_Misc (U9.6), MCU133A_XDS110_MCU (J101.2)
MCU_TCK: MCU133A_F28P55x_Device (U1.60), MCU133A_XDS110_MCU (J101.8)
MCU_TDI: MCU133A_F28P55x_Device (R44.2 R111.1), MCU133A_XDS110_MCU (J101.12)
MCU_TDO: MCU133A_F28P55x_Device (R45.2 R112.1), MCU133A_XDS110_MCU (J101.10)
MCU_TMS: MCU133A_F28P55x_Device (R10.1 U1.62), MCU133A_XDS110_MCU (J101.6)
MCU_TXD: MCU133A_AltRouting_Misc (U9.10), MCU133A_XDS110_MCU (J101.4)
PGA1_IN_N: MCU133A_Connectors (J10.4), MCU133A_AltRouting_Misc (U17.1)
PGA1_IN_P: MCU133A_Connectors (J10.1), MCU133A_AltRouting_Misc (U17.2)
PGA1_IN_P_BP: MCU133A_Connectors (J1/J3.27), MCU133A_AltRouting_Misc (U17.11)
PGA2_IN_N: MCU133A_Connectors (J10.5), MCU133A_AltRouting_Misc (U17.21)
PGA2_IN_P: MCU133A_Connectors (J10.2), MCU133A_AltRouting_Misc (U17.23)
PGA2_IN_P_BP: MCU133A_Connectors (J1/J3.28), MCU133A_AltRouting_Misc (U17.15)
PGA3_IN_N: MCU133A_Connectors (J10.6), MCU133A_AltRouting_Misc (U17.22)
PGA3_IN_N_BP: MCU133A_Connectors (J1/J3.2), MCU133A_AltRouting_Misc (U17.16)
PGA3_IN_P: MCU133A_Connectors (J10.3), MCU133A_AltRouting_Misc (U17.19)
PGA3_IN_P_BP: MCU133A_Connectors (J1/J3.29), MCU133A_AltRouting_Misc (U17.18)
XDS_D_N: MCU133A_USB_and_Power (R1.2), MCU133A_XDS110_MCU (U2.93)
XDS_D_P: MCU133A_USB_and_Power (R2.2), MCU133A_XDS110_MCU (U2.94)
XRSn: MCU133A_Connectors (J4/J2.16 J8/J6.56), MCU133A_F28P55x_Device (C17.1 R11.1 S1.4 U1.2), MCU133A_USB_and_Power (R5.1)

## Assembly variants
001: not fitted C3 C4 C5 C8 C24 C25 C26 C27 C28 C29 C30 C31 C32 C33 C34 C35 C36 C37 C38 C39 C40 C47 C48 C49 C75 C76 C77 C78 C79 C80 C81 C82 C83 C84 C85 C86 C87 C88 C89 C101 C110 FID1 FID2 FID3 FID4 FID5 FID6 R36 R37 R44 R45 R45 R47 R47 R48 R48 R67 R100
